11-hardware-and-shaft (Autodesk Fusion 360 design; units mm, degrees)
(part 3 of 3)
extrude "Extrude2" cut sketch "E Rear Bearing Cap Bolt seed" profile of C1 along normal blind 3 (= "capThickness")
circular_pattern "C-Pattern1" TotalAngle 360
chamfer "Chamfer1" distance 0.3 (= "bedRelief")
work_plane "WorkPlane1" AlongDistance -29 (= "hubFace - adapterThickness") ExtraOffset 0
sketch "F Adapter Flange sketch" plane through (-20.5061, -20.5061, 0) normal (0.7071, 0.7071, 0) x axis (0, 0, 1)
  circle C1 centre (0, 0) radius 38
  dimension "d967" diameter C1 = 76 (= "mountOD")
extrude "Extrude1" new body sketch "F Adapter Flange sketch" along normal blind 6 (= "adapterThickness")
work_plane "WorkPlane2" AlongDistance -23 (= "hubFace") ExtraOffset 0
sketch "F Centering Pilot sketch" plane through (-16.2635, -16.2635, 0) normal (0.7071, 0.7071, 0) x axis (0, 0, 1)
  circle C1 centre (0, 0) radius 25
  circle C2 centre (0, 0) radius 17
  dimension "d972" diameter C1 = 50 (= "pilotDiameter")
  dimension "d973" diameter C2 = 34 (= "pilotInside")
extrude "Extrude2" add sketch "F Centering Pilot sketch" along normal blind 2 (= "pilotHeight")
work_plane "WorkPlane3" AlongDistance -29 (= "hubFace - adapterThickness") ExtraOffset 0
sketch "F Shaft Clearance sketch" plane through (-20.5061, -20.5061, 0) normal (0.7071, 0.7071, 0) x axis (0, 0, 1)
  circle C1 centre (0, 0) radius 4.25
  dimension "d978" diameter C1 = 8.5 (= "shaftClearance")
extrude "Extrude3" cut sketch "F Shaft Clearance sketch" along normal blind 6 (= "adapterThickness")
work_plane "WorkPlane4" AlongDistance -29 (= "hubFace - adapterThickness") ExtraOffset 0
sketch "F Mount Holes" plane through (-20.5061, -20.5061, 0) normal (0.7071, 0.7071, 0) x axis (0, 0, 1)
  circle C1 centre (22.6274, 22.6274) radius 2.15
  circle C2 centre (-22.6274, 22.6274) radius 2.15
  circle C3 centre (-22.6274, -22.6274) radius 2.15
  circle C4 centre (22.6274, -22.6274) radius 2.15
  point P1 (0, 0)
  point P2 (22.6274, 22.6274)
  point P3 (-22.6274, 22.6274)
  point P4 (-22.6274, -22.6274)
  point P5 (22.6274, -22.6274)
  dimension "d983" distance P1 P2 = 22.6274 (= "abs(mountCircle / ( 2 * sqrt(2) ))")
  dimension "d984" distance P1 P2 = 22.6274 (= "abs(mountCircle / ( 2 * sqrt(2) ))")
  dimension "d985" diameter C1 = 4.3 (= "m4Clearance")
  dimension "d986" distance P1 P3 = 22.6274 (= "abs(-mountCircle / ( 2 * sqrt(2) ))")
  dimension "d987" distance P1 P3 = 22.6274 (= "abs(mountCircle / ( 2 * sqrt(2) ))")
  dimension "d988" diameter C2 = 4.3 (= "m4Clearance")
  dimension "d989" distance P1 P4 = 22.6274 (= "abs(-mountCircle / ( 2 * sqrt(2) ))")
  dimension "d990" distance P1 P4 = 22.6274 (= "abs(-mountCircle / ( 2 * sqrt(2) ))")
  dimension "d991" diameter C3 = 4.3 (= "m4Clearance")
  dimension "d992" distance P1 P5 = 22.6274 (= "abs(mountCircle / ( 2 * sqrt(2) ))")
  dimension "d993" distance P1 P5 = 22.6274 (= "abs(-mountCircle / ( 2 * sqrt(2) ))")
  dimension "d994" diameter C4 = 4.3 (= "m4Clearance")
extrude "Extrude4" cut sketch "F Mount Holes" along normal blind 6 (= "adapterThickness")
sketch "F Compression Sleeve Holes" plane through (-20.5061, -20.5061, 0) normal (0.7071, 0.7071, 0) x axis (0, 0, 1)
  line L1 (11.3137, 0) -> (0, 0)
  line L2 (0, 11.3137) -> (0, 0)
  line L3 (-11.3137, 0) -> (0, 0)
  line L4 (0, -11.3137) -> (0, 0)
  circle C1 centre (11.3137, 0) radius 4.1
  circle C2 centre (0, 11.3137) radius 4.1
  circle C3 centre (-11.3137, 0) radius 4.1
  circle C4 centre (0, -11.3137) radius 4.1
  point P1 (0, 0)
  point P2 (11.3137, 0)
  point P3 (0, 11.3137)
  point P5 (0, -11.3137)
  horizontal L1
  vertical L2
  horizontal L3
  vertical L4
  dimension "d997" distance P1 P2 = 11.3137 (= "abs(hubHoleSpacing / sqrt(2))")
  dimension "d998" diameter C1 = 8.2 (= "sleeveOD + sleeveAllowance")
  dimension "d999" distance P1 P3 = 11.3137 (= "abs(hubHoleSpacing / sqrt(2))")
  dimension "d1000" diameter C2 = 8.2 (= "sleeveOD + sleeveAllowance")
  dimension "d59" = 150 (= "bodyWidth")
  dimension "d1002" diameter C3 = 8.2 (= "sleeveOD + sleeveAllowance")
  dimension "d1003" distance P1 P5 = 11.3137 (= "abs(-hubHoleSpacing / sqrt(2))")
  dimension "d1004" diameter C4 = 8.2 (= "sleeveOD + sleeveAllowance")
  dimension "d1001" distance = 11.3137 (= "abs(-hubHoleSpacing / sqrt(2))")
extrude "Extrude5" cut sketch "F Compression Sleeve Holes" profile of C1 C2 C3 C4 along normal blind 6 (= "adapterThickness")
chamfer "Chamfer1" distance 0.4 (= "entryChamfer")
chamfer "Chamfer2" distance 0.3 (= "bedRelief")
work_plane "WorkPlane1" AlongDistance 0.5 (= "qFront") ExtraOffset 0
sketch "Front 608 sketch" plane through (0.3536, 0.3536, 0) normal (0.7071, 0.7071, 0) x axis (0, 0, 1)
  circle C1 centre (0, 0) radius 11
  circle C2 centre (0, 0) radius 4
  dimension "d1011" diameter C1 = 22 (= "bearingOD")
  dimension "d1012" diameter C2 = 8 (= "bearingID")
extrude "Extrude1" new body sketch "Front 608 sketch" along normal blind 7 (= "bearingWidth")
work_plane "WorkPlane2" AlongDistance 25.6 (= "qRearBearing") ExtraOffset 0
sketch "Rear 608 sketch" plane through (18.1019, 18.1019, 0) normal (0.7071, 0.7071, 0) x axis (0, 0, 1)
  circle C1 centre (0, 0) radius 11
  circle C2 centre (0, 0) radius 4
  dimension "d1017" diameter C1 = 22 (= "bearingOD")
  dimension "d1018" diameter C2 = 8 (= "bearingID")
extrude "Extrude2" new body sketch "Rear 608 sketch" along normal blind 7 (= "bearingWidth")
work_plane "WorkPlane1" AlongDistance -24 ExtraOffset 0
sketch "Metal Shaft sketch" plane through (-16.9706, -16.9706, 0) normal (0.7071, 0.7071, 0) x axis (0, 0, 1)
  circle C1 centre (0, 0) radius 4
  dimension "d1023" diameter C1 = 8
extrude "Extrude1" new body sketch "Metal Shaft sketch" along normal blind 60
work_plane "WorkPlane1" AlongDistance -3.5 (= "qFront - 4 mm") ExtraOffset 0
sketch "Front Inner Ring Spacer sketch" plane through (-2.4749, -2.4749, 0) normal (0.7071, 0.7071, 0) x axis (0, 0, 1)
  circle C1 centre (0, 0) radius 5
  circle C2 centre (0, 0) radius 4
  dimension "d1028" diameter C1 = 10
  dimension "d1029" diameter C2 = 8
extrude "Extrude1" new body sketch "Front Inner Ring Spacer sketch" along normal blind 4
work_plane "WorkPlane2" AlongDistance 7.5 (= "qFront + bearingWidth") ExtraOffset 0
sketch "Rear Inner Ring Spacer sketch" plane through (5.3033, 5.3033, 0) normal (0.7071, 0.7071, 0) x axis (0, 0, 1)
  circle C1 centre (0, 0) radius 5
  circle C2 centre (0, 0) radius 4
  dimension "d1034" diameter C1 = 10
  dimension "d1035" diameter C2 = 8
extrude "Extrude2" new body sketch "Rear Inner Ring Spacer sketch" along normal blind 4
work_plane "WorkPlane1" AlongDistance -12.5 (= "qFront - 13 mm") ExtraOffset 0
sketch "Front Collar Maximum Envelope sketch" plane through (-8.8388, -8.8388, 0) normal (0.7071, 0.7071, 0) x axis (0, 0, 1)
  circle C1 centre (0, 0) radius 11.2
  circle C2 centre (0, 0) radius 4
  dimension "d1040" diameter C1 = 22.4
  dimension "d1041" diameter C2 = 8
extrude "Extrude1" new body sketch "Front Collar Maximum Envelope sketch" along normal blind 9
work_plane "WorkPlane2" AlongDistance 11.5 (= "qFront + bearingWidth + 4 mm") ExtraOffset 0
sketch "Rear Collar Maximum Envelope sketch" plane through (8.1317, 8.1317, 0) normal (0.7071, 0.7071, 0) x axis (0, 0, 1)
  circle C1 centre (0, 0) radius 11.2
  circle C2 centre (0, 0) radius 4
  dimension "d1046" diameter C1 = 22.4
  dimension "d1047" diameter C2 = 8
extrude "Extrude2" new body sketch "Rear Collar Maximum Envelope sketch" along normal blind 9
work_plane "WorkPlane1" AlongDistance 0 ExtraOffset 0
sketch "Spacer Pattern Axis" plane through (0, 0, 0) normal (0.7071, 0.7071, 0) x axis (0, 0, 1)
  circle C1 centre (0, 0) radius 0.5
  dimension "d1052" diameter C1 = 1
work_plane "WorkPlane2" AlongDistance 10.6 (= "qFrontBack") ExtraOffset 0
sketch "Support Spacer OD" plane through (7.4953, 7.4953, 0) normal (0.7071, 0.7071, 0) x axis (0, 0, 1)
  line L1 (17, 0) -> (0, 0)
  circle C1 centre (17, 0) radius 3
  circle C2 centre (17, 0) radius 1.6
  point P1 (0, 0)
  point P2 (17, 0)
  horizontal L1
  dimension "d1055" distance P1 P2 = 17 (= "supportCircle / 2")
  dimension "d1056" diameter C1 = 6 (= "supportSpacerOD")
  dimension "d1057" diameter C2 = 3.2
extrude "Extrude1" new body sketch "Support Spacer OD" profile of C1 C2 along normal blind 12 (= "supportSpacer")
circular_pattern "C-Pattern1" TotalAngle 360
work_plane "WorkPlane1" AlongDistance -29 (= "hubFace - adapterThickness") ExtraOffset 0
sketch "Sleeve 1 Outer" plane through (-20.5061, -20.5061, 0) normal (0.7071, 0.7071, 0) x axis (0, 0, 1)
  line L1 (11.3137, 0) -> (0, 0)
  circle C1 centre (11.3137, 0) radius 4
  circle C2 centre (11.3137, 0) radius 2.15
  point P1 (0, 0)
  point P2 (11.3137, 0)
  horizontal L1
  dimension "d1064" distance P1 P2 = 11.3137 (= "abs(hubHoleSpacing / sqrt(2))")
  dimension "d1065" diameter C1 = 8 (= "sleeveOD")
  dimension "d1066" diameter C2 = 4.3
extrude "Extrude1" new body sketch "Sleeve 1 Outer" profile of C1 C2 along normal blind 6 (= "adapterThickness")
work_plane "WorkPlane2" AlongDistance -29 (= "hubFace - adapterThickness") ExtraOffset 0
sketch "Sleeve 2 Outer" plane through (-20.5061, -20.5061, 0) normal (0.7071, 0.7071, 0) x axis (0, 0, 1)
  line L1 (0, 11.3137) -> (0, 0)
  circle C1 centre (0, 11.3137) radius 4
  circle C2 centre (0, 11.3137) radius 2.15
  point P1 (0, 0)
  point P2 (0, 11.3137)
  vertical L1
  dimension "d1071" distance P1 P2 = 11.3137 (= "abs(hubHoleSpacing / sqrt(2))")
  dimension "d1072" diameter C1 = 8 (= "sleeveOD")
  dimension "d1073" diameter C2 = 4.3
extrude "Extrude2" new body sketch "Sleeve 2 Outer" profile of C1 C2 along normal blind 6 (= "adapterThickness")
work_plane "WorkPlane3" AlongDistance -29 (= "hubFace - adapterThickness") ExtraOffset 0
sketch "Sleeve 3 Outer" plane through (-20.5061, -20.5061, 0) normal (0.7071, 0.7071, 0) x axis (0, 0, 1)
  line L1 (-11.3137, 0) -> (0, 0)
  circle C1 centre (-11.3137, 0) radius 4
  circle C2 centre (-11.3137, 0) radius 2.15
  point P1 (0, 0)
  point P2 (-11.3137, 0)
  horizontal L1
  dimension "d1078" distance P1 P2 = 11.3137 (= "abs(-hubHoleSpacing / sqrt(2))")
  dimension "d1079" diameter C1 = 8 (= "sleeveOD")
  dimension "d1080" diameter C2 = 4.3
extrude "Extrude3" new body sketch "Sleeve 3 Outer" profile of C1 C2 along normal blind 6 (= "adapterThickness")
work_plane "WorkPlane4" AlongDistance -29 (= "hubFace - adapterThickness") ExtraOffset 0
sketch "Sleeve 4 Outer" plane through (-20.5061, -20.5061, 0) normal (0.7071, 0.7071, 0) x axis (0, 0, 1)
  line L1 (0, -11.3137) -> (0, 0)
  circle C1 centre (0, -11.3137) radius 4
  circle C2 centre (0, -11.3137) radius 2.15
  point P1 (0, 0)
  point P2 (0, -11.3137)
  vertical L1
  dimension "d1085" distance P1 P2 = 11.3137 (= "abs(-hubHoleSpacing / sqrt(2))")
  dimension "d1086" diameter C1 = 8 (= "sleeveOD")
  dimension "d1087" diameter C2 = 4.3
extrude "Extrude4" new body sketch "Sleeve 4 Outer" profile of C1 C2 along normal blind 6 (= "adapterThickness")
work_plane "WorkPlane1" AlongDistance -23 (= "hubFace") ExtraOffset 0
sketch "Sonic Hub Body sketch" plane through (-16.2635, -16.2635, 0) normal (0.7071, 0.7071, 0) x axis (0, 0, 1)
  circle C1 centre (0, 0) radius 16
  circle C2 centre (0, 0) radius 4
  dimension "d1092" diameter C1 = 32
  dimension "d1093" diameter C2 = 8
extrude "Extrude1" new body sketch "Sonic Hub Body sketch" along normal blind 8
work_plane "WorkPlane2" AlongDistance -15 (= "hubFace + 8 mm") ExtraOffset 0
sketch "Sonic Hub Pilot sketch" plane through (-10.6066, -10.6066, 0) normal (0.7071, 0.7071, 0) x axis (0, 0, 1)
  circle C1 centre (0, 0) radius 7
  circle C2 centre (0, 0) radius 4
  dimension "d1098" diameter C1 = 14
  dimension "d1099" diameter C2 = 8
extrude "Extrude2" add sketch "Sonic Hub Pilot sketch" along normal blind 2
work_plane "WorkPlane3" AlongDistance -23 (= "hubFace") ExtraOffset 0
sketch "Hub M4 Thread Envelopes" plane through (-16.2635, -16.2635, 0) normal (0.7071, 0.7071, 0) x axis (0, 0, 1)
  line L1 (11.3137, 0) -> (0, 0)
  line L2 (0, 11.3137) -> (0, 0)
  line L3 (-11.3137, 0) -> (0, 0)
  line L4 (0, -11.3137) -> (0, 0)
  circle C1 centre (11.3137, 0) radius 2.15
  circle C2 centre (0, 11.3137) radius 2.15
  circle C3 centre (-11.3137, 0) radius 2.15
  circle C4 centre (0, -11.3137) radius 2.15
  point P1 (0, 0)
  point P2 (11.3137, 0)
  point P3 (0, 11.3137)
  point P5 (0, -11.3137)
  horizontal L1
  vertical L2
  horizontal L3
  vertical L4
  dimension "d1104" distance P1 P2 = 11.3137 (= "abs(hubHoleSpacing / sqrt(2))")
  dimension "d1105" diameter C1 = 4.3
  dimension "d1106" distance P1 P3 = 11.3137 (= "abs(hubHoleSpacing / sqrt(2))")
  dimension "d1107" diameter C2 = 4.3
  dimension "d59" = 150 (= "bodyWidth")
  dimension "d1109" diameter C3 = 4.3
  dimension "d1110" distance P1 P5 = 11.3137 (= "abs(-hubHoleSpacing / sqrt(2))")
  dimension "d1111" diameter C4 = 4.3
  dimension "d1108" distance = 11.3137 (= "abs(-hubHoleSpacing / sqrt(2))")
extrude "Extrude3" cut sketch "Hub M4 Thread Envelopes" profile of C1 C2 C3 C4 along normal blind 8
work_plane "WorkPlane1" AlongDistance -30 (= "hubFace - adapterThickness - 1 mm") ExtraOffset 0
sketch "Hub Screw 1 Profile" plane through (-21.2132, -21.2132, 0) normal (0.7071, 0.7071, 0) x axis (0, 0, 1)
  line L1 (11.3137, 0) -> (0, 0)
  circle C1 centre (11.3137, 0) radius 2
  point P1 (0, 0)
  point P2 (11.3137, 0)
  horizontal L1
  dimension "d1116" distance P1 P2 = 11.3137 (= "abs(hubHoleSpacing / sqrt(2))")
  dimension "d1117" diameter C1 = 4
extrude "Extrude1" new body sketch "Hub Screw 1 Profile" profile of C1 along normal blind 12
work_plane "WorkPlane2" AlongDistance -34 (= "hubFace - adapterThickness - 5 mm") ExtraOffset 0
sketch "Hub Screw Head 1 Profile" plane through (-24.0416, -24.0416, 0) normal (0.7071, 0.7071, 0) x axis (0, 0, 1)
  line L1 (11.3137, 0) -> (0, 0)
  circle C1 centre (11.3137, 0) radius 3.5
  point P1 (0, 0)
  point P2 (11.3137, 0)
  horizontal L1
  dimension "d1122" distance P1 P2 = 11.3137 (= "abs(hubHoleSpacing / sqrt(2))")
  dimension "d1123" diameter C1 = 7
extrude "Extrude2" new body sketch "Hub Screw Head 1 Profile" profile of C1 along normal blind 4
work_plane "WorkPlane3" AlongDistance -30 (= "hubFace - adapterThickness - 1 mm") ExtraOffset 0
sketch "Hub Washer 1 Outer" plane through (-21.2132, -21.2132, 0) normal (0.7071, 0.7071, 0) x axis (0, 0, 1)
  line L1 (11.3137, 0) -> (0, 0)
  circle C1 centre (11.3137, 0) radius 6
  circle C2 centre (11.3137, 0) radius 2.15
  point P1 (0, 0)
  point P2 (11.3137, 0)
  horizontal L1
  dimension "d1128" distance P1 P2 = 11.3137 (= "abs(hubHoleSpacing / sqrt(2))")
  dimension "d1129" diameter C1 = 12
  dimension "d1130" diameter C2 = 4.3
extrude "Extrude3" new body sketch "Hub Washer 1 Outer" profile of C1 C2 along normal blind 1
work_plane "WorkPlane4" AlongDistance -30 (= "hubFace - adapterThickness - 1 mm") ExtraOffset 0
sketch "Hub Screw 2 Profile" plane through (-21.2132, -21.2132, 0) normal (0.7071, 0.7071, 0) x axis (0, 0, 1)
  line L1 (0, 11.3137) -> (0, 0)
  circle C1 centre (0, 11.3137) radius 2
  point P1 (0, 0)
  point P2 (0, 11.3137)
  vertical L1
  dimension "d1135" distance P1 P2 = 11.3137 (= "abs(hubHoleSpacing / sqrt(2))")
  dimension "d1136" diameter C1 = 4
extrude "Extrude4" new body sketch "Hub Screw 2 Profile" profile of C1 along normal blind 12
work_plane "WorkPlane5" AlongDistance -34 (= "hubFace - adapterThickness - 5 mm") ExtraOffset 0
sketch "Hub Screw Head 2 Profile" plane through (-24.0416, -24.0416, 0) normal (0.7071, 0.7071, 0) x axis (0, 0, 1)
  line L1 (0, 11.3137) -> (0, 0)
  circle C1 centre (0, 11.3137) radius 3.5
  point P1 (0, 0)
  point P2 (0, 11.3137)
  vertical L1
  dimension "d1141" distance P1 P2 = 11.3137 (= "abs(hubHoleSpacing / sqrt(2))")
  dimension "d1142" diameter C1 = 7
extrude "Extrude5" new body sketch "Hub Screw Head 2 Profile" profile of C1 along normal blind 4
work_plane "WorkPlane6" AlongDistance -30 (= "hubFace - adapterThickness - 1 mm") ExtraOffset 0
sketch "Hub Washer 2 Outer" plane through (-21.2132, -21.2132, 0) normal (0.7071, 0.7071, 0) x axis (0, 0, 1)
  line L1 (0, 11.3137) -> (0, 0)
  circle C1 centre (0, 11.3137) radius 6
  circle C2 centre (0, 11.3137) radius 2.15
  point P1 (0, 0)
  point P2 (0, 11.3137)
  vertical L1
  dimension "d1147" distance P1 P2 = 11.3137 (= "abs(hubHoleSpacing / sqrt(2))")
  dimension "d1148" diameter C1 = 12
  dimension "d1149" diameter C2 = 4.3
extrude "Extrude6" new body sketch "Hub Washer 2 Outer" profile of C1 C2 along normal blind 1
work_plane "WorkPlane7" AlongDistance -30 (= "hubFace - adapterThickness - 1 mm") ExtraOffset 0
sketch "Hub Screw 3 Profile" plane through (-21.2132, -21.2132, 0) normal (0.7071, 0.7071, 0) x axis (0, 0, 1)
  line L1 (-11.3137, 0) -> (0, 0)
  circle C1 centre (-11.3137, 0) radius 2
  point P1 (0, 0)
  point P2 (-11.3137, 0)
  horizontal L1
  dimension "d1154" distance P1 P2 = 11.3137 (= "abs(-hubHoleSpacing / sqrt(2))")
  dimension "d1155" diameter C1 = 4
extrude "Extrude7" new body sketch "Hub Screw 3 Profile" profile of C1 along normal blind 12
work_plane "WorkPlane8" AlongDistance -34 (= "hubFace - adapterThickness - 5 mm") ExtraOffset 0
sketch "Hub Screw Head 3 Profile" plane through (-24.0416, -24.0416, 0) normal (0.7071, 0.7071, 0) x axis (0, 0, 1)
  line L1 (-11.3137, 0) -> (0, 0)
  circle C1 centre (-11.3137, 0) radius 3.5
  point P1 (0, 0)
  point P2 (-11.3137, 0)
  horizontal L1
  dimension "d1160" distance P1 P2 = 11.3137 (= "abs(-hubHoleSpacing / sqrt(2))")
  dimension "d1161" diameter C1 = 7
extrude "Extrude8" new body sketch "Hub Screw Head 3 Profile" profile of C1 along normal blind 4
work_plane "WorkPlane9" AlongDistance -30 (= "hubFace - adapterThickness - 1 mm") ExtraOffset 0
sketch "Hub Washer 3 Outer" plane through (-21.2132, -21.2132, 0) normal (0.7071, 0.7071, 0) x axis (0, 0, 1)
  line L1 (-11.3137, 0) -> (0, 0)
  circle C1 centre (-11.3137, 0) radius 6
  circle C2 centre (-11.3137, 0) radius 2.15
  point P1 (0, 0)
  point P2 (-11.3137, 0)
  horizontal L1
  dimension "d1166" distance P1 P2 = 11.3137 (= "abs(-hubHoleSpacing / sqrt(2))")
  dimension "d1167" diameter C1 = 12
  dimension "d1168" diameter C2 = 4.3
extrude "Extrude9" new body sketch "Hub Washer 3 Outer" profile of C1 C2 along normal blind 1
work_plane "WorkPlane10" AlongDistance -30 (= "hubFace - adapterThickness - 1 mm") ExtraOffset 0
sketch "Hub Screw 4 Profile" plane through (-21.2132, -21.2132, 0) normal (0.7071, 0.7071, 0) x axis (0, 0, 1)
  line L1 (0, -11.3137) -> (0, 0)
  circle C1 centre (0, -11.3137) radius 2
  point P1 (0, 0)
  point P2 (0, -11.3137)
  vertical L1
  dimension "d1173" distance P1 P2 = 11.3137 (= "abs(-hubHoleSpacing / sqrt(2))")
  dimension "d1174" diameter C1 = 4
extrude "Extrude10" new body sketch "Hub Screw 4 Profile" profile of C1 along normal blind 12
work_plane "WorkPlane11" AlongDistance -34 (= "hubFace - adapterThickness - 5 mm") ExtraOffset 0
sketch "Hub Screw Head 4 Profile" plane through (-24.0416, -24.0416, 0) normal (0.7071, 0.7071, 0) x axis (0, 0, 1)
  line L1 (0, -11.3137) -> (0, 0)
  circle C1 centre (0, -11.3137) radius 3.5
  point P1 (0, 0)
  point P2 (0, -11.3137)
  vertical L1
  dimension "d1179" distance P1 P2 = 11.3137 (= "abs(-hubHoleSpacing / sqrt(2))")
  dimension "d1180" diameter C1 = 7
extrude "Extrude11" new body sketch "Hub Screw Head 4 Profile" profile of C1 along normal blind 4
work_plane "WorkPlane12" AlongDistance -30 (= "hubFace - adapterThickness - 1 mm") ExtraOffset 0
sketch "Hub Washer 4 Outer" plane through (-21.2132, -21.2132, 0) normal (0.7071, 0.7071, 0) x axis (0, 0, 1)
  line L1 (0, -11.3137) -> (0, 0)
  circle C1 centre (0, -11.3137) radius 6
  circle C2 centre (0, -11.3137) radius 2.15
  point P1 (0, 0)
  point P2 (0, -11.3137)
  vertical L1
  dimension "d1185" distance P1 P2 = 11.3137 (= "abs(-hubHoleSpacing / sqrt(2))")
  dimension "d1186" diameter C1 = 12
  dimension "d1187" diameter C2 = 4.3
extrude "Extrude12" new body sketch "Hub Washer 4 Outer" profile of C1 C2 along normal blind 1
work_plane "WorkPlane1" AlongDistance -30 (= "hubFace - adapterThickness - 1 mm") ExtraOffset 0
sketch "Adapter Screw 1 Profile" plane through (-21.2132, -21.2132, 0) normal (0.7071, 0.7071, 0) x axis (0, 0, 1)
  circle C1 centre (22.6274, 22.6274) radius 2
  point P1 (0, 0)
  point P2 (22.6274, 22.6274)
  dimension "d1192" distance P1 P2 = 22.6274 (= "abs(mountCircle / ( 2 * sqrt(2) ))")
  dimension "d1193" distance P1 P2 = 22.6274 (= "abs(mountCircle / ( 2 * sqrt(2) ))")
  dimension "d1194" diameter C1 = 4
extrude "Extrude1" new body sketch "Adapter Screw 1 Profile" along normal blind 30
work_plane "WorkPlane2" AlongDistance -34 (= "hubFace - adapterThickness - 5 mm") ExtraOffset 0
sketch "Adapter Screw Head 1 Profile" plane through (-24.0416, -24.0416, 0) normal (0.7071, 0.7071, 0) x axis (0, 0, 1)
  circle C1 centre (22.6274, 22.6274) radius 3.5
  point P1 (0, 0)
  point P2 (22.6274, 22.6274)
  dimension "d1199" distance P1 P2 = 22.6274 (= "abs(mountCircle / ( 2 * sqrt(2) ))")
  dimension "d1200" distance P1 P2 = 22.6274 (= "abs(mountCircle / ( 2 * sqrt(2) ))")
  dimension "d1201" diameter C1 = 7
extrude "Extrude2" new body sketch "Adapter Screw Head 1 Profile" along normal blind 4
work_plane "WorkPlane3" AlongDistance -30 (= "hubFace - adapterThickness - 1 mm") ExtraOffset 0
sketch "Adapter Washer 1 Outer" plane through (-21.2132, -21.2132, 0) normal (0.7071, 0.7071, 0) x axis (0, 0, 1)
  circle C1 centre (22.6274, 22.6274) radius 4.5
  circle C2 centre (22.6274, 22.6274) radius 2.15
  point P1 (0, 0)
  point P2 (22.6274, 22.6274)
  dimension "d1206" distance P1 P2 = 22.6274 (= "abs(mountCircle / ( 2 * sqrt(2) ))")
  dimension "d1207" distance P1 P2 = 22.6274 (= "abs(mountCircle / ( 2 * sqrt(2) ))")
  dimension "d1208" diameter C1 = 9
  dimension "d1209" diameter C2 = 4.3
extrude "Extrude3" new body sketch "Adapter Washer 1 Outer" along normal blind 1
work_plane "WorkPlane4" ExtraOffset 0
sketch "Adapter Nut Hex 1" plane through (-3.182, -3.182, 0) normal (0.7071, 0.7071, 0) x axis (0, 0, 1)
  line L1 (24.6481, 26.1274) -> (26.6689, 22.6274)
  line L2 (20.6067, 26.1274) -> (24.6481, 26.1274)
  line L3 (18.586, 22.6274) -> (20.6067, 26.1274)
  line L4 (20.6067, 19.1274) -> (18.586, 22.6274)
  line L5 (24.6481, 19.1274) -> (20.6067, 19.1274)
  line L6 (26.6689, 22.6274) -> (24.6481, 19.1274)
  circle C1 centre (22.6274, 22.6274) radius 4.0415
  point P3 (26.6689, 22.6274)
  point P4 (24.6481, 26.1274)
  point P5 (20.6067, 26.1274)
  point P6 (18.586, 22.6274)
  point P7 (20.6067, 19.1274)
  point P8 (24.6481, 19.1274)
  point P1 (0, 0)
  point P2 (22.6274, 22.6274)
  coincident C1 P3
  coincident C1 P4
  coincident C1 P5
  coincident C1 P6
  coincident C1 P7
  coincident C1 P8
  equal L1 L2
  equal L1 L3
  equal L1 L4
  equal L1 L5
  equal L1 L6
  horizontal L2
  dimension "d1214" distance P1 P2 = 22.6274 (= "abs(mountCircle / ( 2 * sqrt(2) ))")
  dimension "d1215" distance P1 P2 = 22.6274 (= "abs(mountCircle / ( 2 * sqrt(2) ))")
  dimension "d1216" diameter C1 = 8.0829 (= "2 * ( 7 mm ) / sqrt(3)")
extrude "Extrude4" new body sketch "Adapter Nut Hex 1" profile of L1 L2 L3 L4 L5 L6 along normal blind 3.2
sketch "Nut Thread Clearance 1" plane through (-3.182, -3.182, 0) normal (0.7071, 0.7071, 0) x axis (0, 0, 1)
  circle C1 centre (22.6274, 22.6274) radius 2.15
  point P1 (0, 0)
  point P2 (22.6274, 22.6274)
  dimension "d1219" distance P1 P2 = 22.6274 (= "abs(mountCircle / ( 2 * sqrt(2) ))")
  dimension "d1220" distance P1 P2 = 22.6274 (= "abs(mountCircle / ( 2 * sqrt(2) ))")
  dimension "d1221" diameter C1 = 4.3
extrude "Extrude5" cut sketch "Nut Thread Clearance 1" along normal blind 3.2
work_plane "WorkPlane5" AlongDistance -30 (= "hubFace - adapterThickness - 1 mm") ExtraOffset 0
sketch "Adapter Screw 2 Profile" plane through (-21.2132, -21.2132, 0) normal (0.7071, 0.7071, 0) x axis (0, 0, 1)
  circle C1 centre (-22.6274, 22.6274) radius 2
  point P1 (0, 0)
  point P2 (-22.6274, 22.6274)
  dimension "d1226" distance P1 P2 = 22.6274 (= "abs(-mountCircle / ( 2 * sqrt(2) ))")
  dimension "d1227" distance P1 P2 = 22.6274 (= "abs(mountCircle / ( 2 * sqrt(2) ))")
  dimension "d1228" diameter C1 = 4
extrude "Extrude6" new body sketch "Adapter Screw 2 Profile" along normal blind 30
work_plane "WorkPlane6" AlongDistance -34 (= "hubFace - adapterThickness - 5 mm") ExtraOffset 0
sketch "Adapter Screw Head 2 Profile" plane through (-24.0416, -24.0416, 0) normal (0.7071, 0.7071, 0) x axis (0, 0, 1)
  circle C1 centre (-22.6274, 22.6274) radius 3.5
  point P1 (0, 0)
  point P2 (-22.6274, 22.6274)
  dimension "d1233" distance P1 P2 = 22.6274 (= "abs(-mountCircle / ( 2 * sqrt(2) ))")
  dimension "d1234" distance P1 P2 = 22.6274 (= "abs(mountCircle / ( 2 * sqrt(2) ))")
  dimension "d1235" diameter C1 = 7
extrude "Extrude7" new body sketch "Adapter Screw Head 2 Profile" along normal blind 4
work_plane "WorkPlane7" AlongDistance -30 (= "hubFace - adapterThickness - 1 mm") ExtraOffset 0
sketch "Adapter Washer 2 Outer" plane through (-21.2132, -21.2132, 0) normal (0.7071, 0.7071, 0) x axis (0, 0, 1)
  circle C1 centre (-22.6274, 22.6274) radius 4.5
  circle C2 centre (-22.6274, 22.6274) radius 2.15
  point P1 (0, 0)
  point P2 (-22.6274, 22.6274)
  dimension "d1240" distance P1 P2 = 22.6274 (= "abs(-mountCircle / ( 2 * sqrt(2) ))")
  dimension "d1241" distance P1 P2 = 22.6274 (= "abs(mountCircle / ( 2 * sqrt(2) ))")
  dimension "d1242" diameter C1 = 9
  dimension "d1243" diameter C2 = 4.3
extrude "Extrude8" new body sketch "Adapter Washer 2 Outer" along normal blind 1
work_plane "WorkPlane8" ExtraOffset 0
sketch "Adapter Nut Hex 2" plane through (-3.182, -3.182, 0) normal (0.7071, 0.7071, 0) x axis (0, 0, 1)
  line L1 (-20.6067, 26.1274) -> (-18.586, 22.6274)
  line L2 (-24.6481, 26.1274) -> (-20.6067, 26.1274)
  line L3 (-26.6689, 22.6274) -> (-24.6481, 26.1274)
  line L4 (-24.6481, 19.1274) -> (-26.6689, 22.6274)
  line L5 (-20.6067, 19.1274) -> (-24.6481, 19.1274)
  line L6 (-18.586, 22.6274) -> (-20.6067, 19.1274)
  circle C1 centre (-22.6274, 22.6274) radius 4.0415
  point P3 (-18.586, 22.6274)
  point P4 (-20.6067, 26.1274)
  point P5 (-24.6481, 26.1274)
  point P6 (-26.6689, 22.6274)
  point P7 (-24.6481, 19.1274)
  point P8 (-20.6067, 19.1274)
  point P1 (0, 0)
  point P2 (-22.6274, 22.6274)
  coincident C1 P3
  coincident C1 P4
  coincident C1 P5
  coincident C1 P6
  coincident C1 P7
  coincident C1 P8
  equal L1 L2
  equal L1 L3
  equal L1 L4
  equal L1 L5
  equal L1 L6
  horizontal L2
  dimension "d1248" distance P1 P2 = 22.6274 (= "abs(-mountCircle / ( 2 * sqrt(2) ))")
  dimension "d1249" distance P1 P2 = 22.6274 (= "abs(mountCircle / ( 2 * sqrt(2) ))")
  dimension "d1250" diameter C1 = 8.0829 (= "2 * ( 7 mm ) / sqrt(3)")
extrude "Extrude9" new body sketch "Adapter Nut Hex 2" profile of L1 L2 L3 L4 L5 L6 along normal blind 3.2
sketch "Nut Thread Clearance 2" plane through (-3.182, -3.182, 0) normal (0.7071, 0.7071, 0) x axis (0, 0, 1)
  circle C1 centre (-22.6274, 22.6274) radius 2.15
  point P1 (0, 0)
  point P2 (-22.6274, 22.6274)
  dimension "d1253" distance P1 P2 = 22.6274 (= "abs(-mountCircle / ( 2 * sqrt(2) ))")
  dimension "d1254" distance P1 P2 = 22.6274 (= "abs(mountCircle / ( 2 * sqrt(2) ))")
  dimension "d1255" diameter C1 = 4.3
extrude "Extrude10" cut sketch "Nut Thread Clearance 2" along normal blind 3.2
work_plane "WorkPlane9" AlongDistance -30 (= "hubFace - adapterThickness - 1 mm") ExtraOffset 0
sketch "Adapter Screw 3 Profile" plane through (-21.2132, -21.2132, 0) normal (0.7071, 0.7071, 0) x axis (0, 0, 1)
  circle C1 centre (-22.6274, -22.6274) radius 2
  point P1 (0, 0)
  point P2 (-22.6274, -22.6274)
  dimension "d1260" distance P1 P2 = 22.6274 (= "abs(-mountCircle / ( 2 * sqrt(2) ))")
  dimension "d1261" distance P1 P2 = 22.6274 (= "abs(-mountCircle / ( 2 * sqrt(2) ))")
  dimension "d1262" diameter C1 = 4
extrude "Extrude11" new body sketch "Adapter Screw 3 Profile" along normal blind 30
work_plane "WorkPlane10" AlongDistance -34 (= "hubFace - adapterThickness - 5 mm") ExtraOffset 0
sketch "Adapter Screw Head 3 Profile" plane through (-24.0416, -24.0416, 0) normal (0.7071, 0.7071, 0) x axis (0, 0, 1)
  circle C1 centre (-22.6274, -22.6274) radius 3.5
  point P1 (0, 0)
  point P2 (-22.6274, -22.6274)
  dimension "d1267" distance P1 P2 = 22.6274 (= "abs(-mountCircle / ( 2 * sqrt(2) ))")
  dimension "d1268" distance P1 P2 = 22.6274 (= "abs(-mountCircle / ( 2 * sqrt(2) ))")
  dimension "d1269" diameter C1 = 7
extrude "Extrude12" new body sketch "Adapter Screw Head 3 Profile" along normal blind 4
work_plane "WorkPlane11" AlongDistance -30 (= "hubFace - adapterThickness - 1 mm") ExtraOffset 0
sketch "Adapter Washer 3 Outer" plane through (-21.2132, -21.2132, 0) normal (0.7071, 0.7071, 0) x axis (0, 0, 1)
  circle C1 centre (-22.6274, -22.6274) radius 4.5
  circle C2 centre (-22.6274, -22.6274) radius 2.15
  point P1 (0, 0)
  point P2 (-22.6274, -22.6274)
  dimension "d1274" distance P1 P2 = 22.6274 (= "abs(-mountCircle / ( 2 * sqrt(2) ))")
  dimension "d1275" distance P1 P2 = 22.6274 (= "abs(-mountCircle / ( 2 * sqrt(2) ))")
  dimension "d1276" diameter C1 = 9
  dimension "d1277" diameter C2 = 4.3
extrude "Extrude13" new body sketch "Adapter Washer 3 Outer" along normal blind 1
work_plane "WorkPlane12" ExtraOffset 0
sketch "Adapter Nut Hex 3" plane through (-3.182, -3.182, 0) normal (0.7071, 0.7071, 0) x axis (0, 0, 1)
  line L1 (-20.6067, -19.1274) -> (-18.586, -22.6274)
  line L2 (-24.6481, -19.1274) -> (-20.6067, -19.1274)
  line L3 (-26.6689, -22.6274) -> (-24.6481, -19.1274)
  line L4 (-24.6481, -26.1274) -> (-26.6689, -22.6274)
  line L5 (-20.6067, -26.1274) -> (-24.6481, -26.1274)
  line L6 (-18.586, -22.6274) -> (-20.6067, -26.1274)
  circle C1 centre (-22.6274, -22.6274) radius 4.0415
  point P3 (-18.586, -22.6274)
  point P4 (-20.6067, -19.1274)
  point P5 (-24.6481, -19.1274)
  point P6 (-26.6689, -22.6274)
  point P7 (-24.6481, -26.1274)
  point P8 (-20.6067, -26.1274)
  point P1 (0, 0)
  point P2 (-22.6274, -22.6274)
  coincident C1 P3
  coincident C1 P4
  coincident C1 P5
  coincident C1 P6
  coincident C1 P7
  coincident C1 P8
  equal L1 L2
  equal L1 L3
  equal L1 L4
  equal L1 L5
  equal L1 L6
  horizontal L2
  dimension "d1282" distance P1 P2 = 22.6274 (= "abs(-mountCircle / ( 2 * sqrt(2) ))")
  dimension "d1283" distance P1 P2 = 22.6274 (= "abs(-mountCircle / ( 2 * sqrt(2) ))")
  dimension "d1284" diameter C1 = 8.0829 (= "2 * ( 7 mm ) / sqrt(3)")
extrude "Extrude14" new body sketch "Adapter Nut Hex 3" profile of L1 L2 L3 L4 L5 L6 along normal blind 3.2
sketch "Nut Thread Clearance 3" plane through (-3.182, -3.182, 0) normal (0.7071, 0.7071, 0) x axis (0, 0, 1)
  circle C1 centre (-22.6274, -22.6274) radius 2.15
  point P1 (0, 0)
  point P2 (-22.6274, -22.6274)
  dimension "d1287" distance P1 P2 = 22.6274 (= "abs(-mountCircle / ( 2 * sqrt(2) ))")
  dimension "d1288" distance P1 P2 = 22.6274 (= "abs(-mountCircle / ( 2 * sqrt(2) ))")
  dimension "d1289" diameter C1 = 4.3
extrude "Extrude15" cut sketch "Nut Thread Clearance 3" along normal blind 3.2
work_plane "WorkPlane13" AlongDistance -30 (= "hubFace - adapterThickness - 1 mm") ExtraOffset 0
sketch "Adapter Screw 4 Profile" plane through (-21.2132, -21.2132, 0) normal (0.7071, 0.7071, 0) x axis (0, 0, 1)
  circle C1 centre (22.6274, -22.6274) radius 2
  point P1 (0, 0)
  point P2 (22.6274, -22.6274)
  dimension "d1294" distance P1 P2 = 22.6274 (= "abs(mountCircle / ( 2 * sqrt(2) ))")
  dimension "d1295" distance P1 P2 = 22.6274 (= "abs(-mountCircle / ( 2 * sqrt(2) ))")
  dimension "d1296" diameter C1 = 4
extrude "Extrude16" new body sketch "Adapter Screw 4 Profile" along normal blind 30
work_plane "WorkPlane14" AlongDistance -34 (= "hubFace - adapterThickness - 5 mm") ExtraOffset 0
sketch "Adapter Screw Head 4 Profile" plane through (-24.0416, -24.0416, 0) normal (0.7071, 0.7071, 0) x axis (0, 0, 1)
  circle C1 centre (22.6274, -22.6274) radius 3.5
  point P1 (0, 0)
  point P2 (22.6274, -22.6274)
  dimension "d1301" distance P1 P2 = 22.6274 (= "abs(mountCircle / ( 2 * sqrt(2) ))")
  dimension "d1302" distance P1 P2 = 22.6274 (= "abs(-mountCircle / ( 2 * sqrt(2) ))")
  dimension "d1303" diameter C1 = 7
extrude "Extrude17" new body sketch "Adapter Screw Head 4 Profile" along normal blind 4
work_plane "WorkPlane15" AlongDistance -30 (= "hubFace - adapterThickness - 1 mm") ExtraOffset 0
sketch "Adapter Washer 4 Outer" plane through (-21.2132, -21.2132, 0) normal (0.7071, 0.7071, 0) x axis (0, 0, 1)
  circle C1 centre (22.6274, -22.6274) radius 4.5
  circle C2 centre (22.6274, -22.6274) radius 2.15
  point P1 (0, 0)
  point P2 (22.6274, -22.6274)
  dimension "d1308" distance P1 P2 = 22.6274 (= "abs(mountCircle / ( 2 * sqrt(2) ))")
  dimension "d1309" distance P1 P2 = 22.6274 (= "abs(-mountCircle / ( 2 * sqrt(2) ))")
  dimension "d1310" diameter C1 = 9
  dimension "d1311" diameter C2 = 4.3
extrude "Extrude18" new body sketch "Adapter Washer 4 Outer" along normal blind 1
work_plane "WorkPlane16" ExtraOffset 0
sketch "Adapter Nut Hex 4" plane through (-3.182, -3.182, 0) normal (0.7071, 0.7071, 0) x axis (0, 0, 1)
  line L1 (24.6481, -19.1274) -> (26.6689, -22.6274)
  line L2 (20.6067, -19.1274) -> (24.6481, -19.1274)
  line L3 (18.586, -22.6274) -> (20.6067, -19.1274)
  line L4 (20.6067, -26.1274) -> (18.586, -22.6274)
  line L5 (24.6481, -26.1274) -> (20.6067, -26.1274)
  line L6 (26.6689, -22.6274) -> (24.6481, -26.1274)
  circle C1 centre (22.6274, -22.6274) radius 4.0415
  point P3 (26.6689, -22.6274)
  point P4 (24.6481, -19.1274)
  point P5 (20.6067, -19.1274)
  point P6 (18.586, -22.6274)
  point P7 (20.6067, -26.1274)
  point P8 (24.6481, -26.1274)
  point P1 (0, 0)
  point P2 (22.6274, -22.6274)
  coincident C1 P3
  coincident C1 P4
  coincident C1 P5
  coincident C1 P6
  coincident C1 P7
  coincident C1 P8
  equal L1 L2
  equal L1 L3
  equal L1 L4
  equal L1 L5
  equal L1 L6
  horizontal L2
  dimension "d1316" distance P1 P2 = 22.6274 (= "abs(mountCircle / ( 2 * sqrt(2) ))")
  dimension "d1317" distance P1 P2 = 22.6274 (= "abs(-mountCircle / ( 2 * sqrt(2) ))")
  dimension "d1318" diameter C1 = 8.0829 (= "2 * ( 7 mm ) / sqrt(3)")
extrude "Extrude19" new body sketch "Adapter Nut Hex 4" profile of L1 L2 L3 L4 L5 L6 along normal blind 3.2
sketch "Nut Thread Clearance 4" plane through (-3.182, -3.182, 0) normal (0.7071, 0.7071, 0) x axis (0, 0, 1)
  circle C1 centre (22.6274, -22.6274) radius 2.15
  point P1 (0, 0)
  point P2 (22.6274, -22.6274)
  dimension "d1321" distance P1 P2 = 22.6274 (= "abs(mountCircle / ( 2 * sqrt(2) ))")
  dimension "d1322" distance P1 P2 = 22.6274 (= "abs(-mountCircle / ( 2 * sqrt(2) ))")
  dimension "d1323" diameter C1 = 4.3
extrude "Extrude20" cut sketch "Nut Thread Clearance 4" along normal blind 3.2
work_plane "WorkPlane1" AlongDistance 0 ExtraOffset 0
sketch "M3 Pattern Axis" plane through (0, 0, 0) normal (0.7071, 0.7071, 0) x axis (0, 0, 1)
  circle C1 centre (0, 0) radius 0.5
  dimension "d1328" diameter C1 = 1
work_plane "WorkPlane2" AlongDistance -8.7 (= "qRearEnd + capThickness + 0.5 mm - 45 mm") ExtraOffset 0
sketch "M3 Shank Profile" plane through (-6.1518, -6.1518, 0) normal (0.7071, 0.7071, 0) x axis (0, 0, 1)
  line L1 (17, 0) -> (0, 0)
  circle C1 centre (17, 0) radius 1.5
  point P1 (0, 0)
  point P2 (17, 0)
  horizontal L1
  dimension "d1331" distance P1 P2 = 17 (= "supportCircle / 2")
  dimension "d1332" diameter C1 = 3
extrude "Extrude1" new body sketch "M3 Shank Profile" profile of C1 along normal blind 45
work_plane "WorkPlane3" AlongDistance 36.3 (= "qRearEnd + capThickness + 0.5 mm") ExtraOffset 0
sketch "M3 Head Profile" plane through (25.668, 25.668, 0) normal (0.7071, 0.7071, 0) x axis (0, 0, 1)
  line L1 (17, 0) -> (0, 0)
  circle C1 centre (17, 0) radius 2.75
  point P1 (0, 0)
  point P2 (17, 0)
  horizontal L1
  dimension "d1337" distance P1 P2 = 17 (= "supportCircle / 2")
  dimension "d1338" diameter C1 = 5.5
extrude "Extrude2" new body sketch "M3 Head Profile" profile of C1 along normal blind 3
work_plane "WorkPlane4" AlongDistance 35.8 (= "qRearEnd + capThickness") ExtraOffset 0
sketch "Rear M3 Washer Profile" plane through (25.3144, 25.3144, 0) normal (0.7071, 0.7071, 0) x axis (0, 0, 1)
  line L1 (17, 0) -> (0, 0)
  circle C1 centre (17, 0) radius 3.5
  circle C2 centre (17, 0) radius 1.65
  point P1 (0, 0)
  point P2 (17, 0)
  horizontal L1
  dimension "d1343" distance P1 P2 = 17 (= "supportCircle / 2")
  dimension "d1344" diameter C1 = 7
  dimension "d1345" diameter C2 = 3.3
extrude "Extrude3" new body sketch "Rear M3 Washer Profile" profile of C1 C2 along normal blind 0.5
work_plane "WorkPlane5" AlongDistance -3 (= "qFront - capThickness - 0.5 mm") ExtraOffset 0
sketch "Front M3 Washer Profile" plane through (-2.1213, -2.1213, 0) normal (0.7071, 0.7071, 0) x axis (0, 0, 1)
  line L1 (17, 0) -> (0, 0)
  circle C1 centre (17, 0) radius 3.5
  circle C2 centre (17, 0) radius 1.65
  point P1 (0, 0)
  point P2 (17, 0)
  horizontal L1
  dimension "d1350" distance P1 P2 = 17 (= "supportCircle / 2")
  dimension "d1351" diameter C1 = 7
  dimension "d1352" diameter C2 = 3.3
extrude "Extrude4" new body sketch "Front M3 Washer Profile" profile of C1 C2 along normal blind 0.5
work_plane "WorkPlane6" AlongDistance -7 (= "qFront - capThickness - 4.5 mm") ExtraOffset 0
sketch "Front M3 Nyloc Envelope Profile" plane through (-4.9497, -4.9497, 0) normal (0.7071, 0.7071, 0) x axis (0, 0, 1)
  line L1 (17, 0) -> (0, 0)
  circle C1 centre (17, 0) radius 3.18
  circle C2 centre (17, 0) radius 1.65
  point P1 (0, 0)
  point P2 (17, 0)
  horizontal L1
  dimension "d1357" distance P1 P2 = 17 (= "supportCircle / 2")
  dimension "d1358" diameter C1 = 6.36
  dimension "d1359" diameter C2 = 3.3
extrude "Extrude5" new body sketch "Front M3 Nyloc Envelope Profile" profile of C1 C2 along normal blind 4
circular_pattern "C-Pattern1" TotalAngle 360
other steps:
base_feature "Base Feature1" bodies "A Housing print"
base_feature "Base Feature1" bodies "B Moving Body print"
create_component "CreateComponent1"
reparent_decal "ReparentDecal1"
remove_body "RemoveBody1"
create_component "CreateComponent2"
reparent_decal "ReparentDecal2"
remove_body "RemoveBody2"
create_component "CreateComponent3"
create_component "CreateComponent4"
create_component "CreateComponent5"
create_component "CreateComponent6"
create_component "CreateComponent7"
create_component "CreateComponent8"
create_component "CreateComponent9"
create_component "CreateComponent10"
create_component "CreateComponent11"
create_component "CreateComponent12"
create_component "CreateComponent13"
create_component "CreateComponent14"
create_component "CreateComponent15"
create_component "CreateComponent16"
named bodies: "A Housing print", "B Moving Body print"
